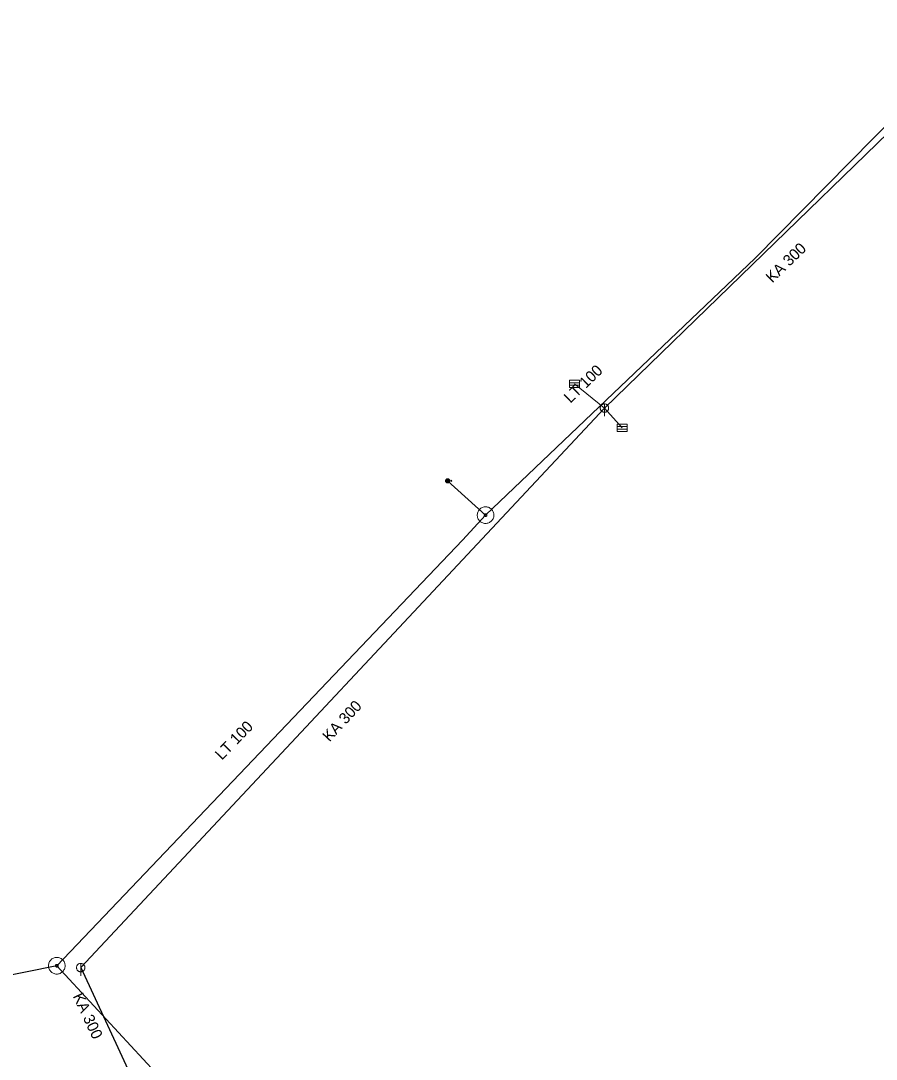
# Model space of a CAD drawing. Extents: x -687515 to -686506, y -974029 to -973461.
# Drawn here: x -687114.7 to -687063.3, y -973836.1 to -973773.7 of the extents above; entities that cross this region are included whole.
import ezdxf
from ezdxf.enums import TextEntityAlignment as Align

# ---------------------------------------------------------------- set-up
doc = ezdxf.new("R2010")
doc.units = 0
doc.header["$LTSCALE"] = 0.27
for name, color, linetype, lineweight in [('1', 7, 'Continuous', 13), ('11', 7, 'Continuous', 13), ('14', 7, 'Continuous', 25), ('17', 7, 'Continuous', 25), ('22', 7, 'Continuous', 13), ('47', 7, 'Continuous', 13), ('9', 7, 'Continuous', 13)]:
    doc.layers.add(name, color=color, linetype=linetype, lineweight=lineweight)

msp = doc.modelspace()

# ---------------------------------------------------------------- linework, layer by layer
at = {"layer": '11'}
for p in [(-687081.398, -973795.561), (-687078.524, -973798.199)]:
    msp.add_line(p, (-687079.592, -973797.014), dxfattribs=at)
at = {"layer": '14'}
for p, q in [((-687057.566, -973775.642), (-687079.592, -973797.014)), ((-687079.592, -973797.014), (-687111.064, -973830.634)), ((-687111.064, -973830.634), (-687107.04, -973839.305))]:
    msp.add_line(p, q, dxfattribs=at)
at = {"layer": '14', "lineweight": 13}
for p, q in [((-687086.733, -973803.447), (-687089.012, -973801.388)), ((-687106.566, -973836.941), (-687112.499, -973830.523))]:
    msp.add_line(p, q, dxfattribs=at)
at = {"layer": '17'}
for points in [[(-686989.707, -973753.404), (-687001.294, -973755.738), (-687033.846, -973763.506), (-687042.734, -973766.009), (-687045.081, -973767.522), (-687056.296, -973773.572), (-687070.532, -973788), (-687086.733, -973803.447)], [(-687112.499, -973830.523), (-687125.387, -973833.14), (-687131.526, -973833.246), (-687138.067, -973830.845), (-687146.977, -973822.133), (-687188.57, -973780.435), (-687198.6, -973770.76), (-687208.769, -973760.209)], [(-687086.733, -973803.447), (-687088.12, -973804.949), (-687112.499, -973830.523)]]:
    msp.add_lwpolyline(points, dxfattribs=at)
at = {"layer": '22'}
for p, q in [((-687081.693, -973795.49), (-687081.095, -973795.49)), ((-687081.693, -973795.636), (-687081.095, -973795.636)), ((-687079.591, -973796.762), (-687079.592, -973797.505)), ((-687078.819, -973798.128), (-687078.221, -973798.128)), ((-687078.819, -973798.274), (-687078.221, -973798.274)), ((-687111.063, -973830.382), (-687111.064, -973831.125))]:
    msp.add_line(p, q, dxfattribs=at)
for points in [[(-687081.693, -973795.344), (-687081.095, -973795.344), (-687081.095, -973795.781), (-687081.693, -973795.781)], [(-687079.34, -973797.014), (-687079.341, -973796.988), (-687079.345, -973796.962), (-687079.351, -973796.936), (-687079.361, -973796.912), (-687079.373, -973796.888), (-687079.387, -973796.866), (-687079.404, -973796.845), (-687079.422, -973796.827), (-687079.443, -973796.81), (-687079.465, -973796.796), (-687079.489, -973796.784), (-687079.513, -973796.774), (-687079.539, -973796.768), (-687079.565, -973796.764), (-687079.591, -973796.762), (-687079.617, -973796.763), (-687079.643, -973796.767), (-687079.669, -973796.773), (-687079.694, -973796.783), (-687079.717, -973796.795), (-687079.739, -973796.809), (-687079.76, -973796.826), (-687079.778, -973796.844), (-687079.795, -973796.865), (-687079.809, -973796.887), (-687079.821, -973796.911), (-687079.831, -973796.935), (-687079.838, -973796.961), (-687079.842, -973796.987), (-687079.843, -973797.013), (-687079.843, -973797.039), (-687079.839, -973797.065), (-687079.832, -973797.091), (-687079.822, -973797.116), (-687079.81, -973797.139), (-687079.796, -973797.161), (-687079.779, -973797.182), (-687079.761, -973797.2), (-687079.74, -973797.217), (-687079.718, -973797.231), (-687079.695, -973797.243), (-687079.67, -973797.253), (-687079.644, -973797.26), (-687079.618, -973797.264), (-687079.592, -973797.266), (-687079.566, -973797.265), (-687079.54, -973797.261), (-687079.514, -973797.254), (-687079.49, -973797.244), (-687079.466, -973797.232), (-687079.444, -973797.218), (-687079.423, -973797.201), (-687079.405, -973797.183), (-687079.388, -973797.162), (-687079.374, -973797.14), (-687079.362, -973797.117), (-687079.352, -973797.092), (-687079.346, -973797.066), (-687079.342, -973797.04)], [(-687078.819, -973797.982), (-687078.221, -973797.982), (-687078.221, -973798.419), (-687078.819, -973798.419)], [(-687110.812, -973830.634), (-687110.813, -973830.608), (-687110.817, -973830.582), (-687110.823, -973830.556), (-687110.833, -973830.532), (-687110.845, -973830.508), (-687110.859, -973830.486), (-687110.876, -973830.465), (-687110.894, -973830.447), (-687110.915, -973830.43), (-687110.937, -973830.416), (-687110.961, -973830.404), (-687110.985, -973830.394), (-687111.011, -973830.388), (-687111.037, -973830.384), (-687111.063, -973830.382), (-687111.089, -973830.383), (-687111.115, -973830.387), (-687111.141, -973830.393), (-687111.166, -973830.403), (-687111.189, -973830.415), (-687111.211, -973830.429), (-687111.232, -973830.446), (-687111.25, -973830.464), (-687111.267, -973830.485), (-687111.281, -973830.507), (-687111.293, -973830.531), (-687111.303, -973830.555), (-687111.31, -973830.581), (-687111.314, -973830.607), (-687111.316, -973830.633), (-687111.315, -973830.659), (-687111.311, -973830.685), (-687111.304, -973830.711), (-687111.294, -973830.736), (-687111.282, -973830.759), (-687111.268, -973830.781), (-687111.251, -973830.802), (-687111.233, -973830.82), (-687111.212, -973830.837), (-687111.19, -973830.851), (-687111.167, -973830.863), (-687111.142, -973830.873), (-687111.116, -973830.88), (-687111.09, -973830.884), (-687111.064, -973830.886), (-687111.038, -973830.885), (-687111.012, -973830.881), (-687110.986, -973830.874), (-687110.962, -973830.864), (-687110.938, -973830.852), (-687110.916, -973830.838), (-687110.895, -973830.821), (-687110.877, -973830.803), (-687110.86, -973830.782), (-687110.846, -973830.76), (-687110.834, -973830.737), (-687110.824, -973830.712), (-687110.818, -973830.686), (-687110.814, -973830.66)]]:
    msp.add_lwpolyline(points, close=True, dxfattribs=at)
at = {"layer": '47'}
for points in [[(-687086.426, -973803.051), (-687086.469, -973803.022), (-687086.515, -973802.996), (-687086.564, -973802.977), (-687086.613, -973802.961), (-687086.665, -973802.951), (-687086.718, -973802.947), (-687086.77, -973802.949), (-687086.821, -973802.955), (-687086.872, -973802.967), (-687086.922, -973802.984), (-687086.97, -973803.006), (-687087.014, -973803.034), (-687087.056, -973803.065), (-687087.094, -973803.101), (-687087.128, -973803.14), (-687087.157, -973803.183), (-687087.183, -973803.229), (-687087.203, -973803.278), (-687087.218, -973803.327), (-687087.228, -973803.379), (-687087.232, -973803.432), (-687087.231, -973803.484), (-687087.224, -973803.536), (-687087.213, -973803.587), (-687087.195, -973803.636), (-687087.173, -973803.684), (-687087.146, -973803.729), (-687087.114, -973803.77), (-687087.078, -973803.808), (-687087.039, -973803.842), (-687086.996, -973803.871), (-687086.95, -973803.897), (-687086.901, -973803.918), (-687086.852, -973803.932), (-687086.8, -973803.942), (-687086.748, -973803.947), (-687086.695, -973803.946), (-687086.643, -973803.939), (-687086.592, -973803.927), (-687086.543, -973803.909), (-687086.495, -973803.887), (-687086.451, -973803.86), (-687086.409, -973803.828), (-687086.371, -973803.792), (-687086.337, -973803.753), (-687086.308, -973803.71), (-687086.282, -973803.664), (-687086.262, -973803.616), (-687086.247, -973803.566), (-687086.237, -973803.514), (-687086.232, -973803.462), (-687086.234, -973803.41), (-687086.241, -973803.358), (-687086.253, -973803.307), (-687086.27, -973803.257), (-687086.292, -973803.209), (-687086.319, -973803.166), (-687086.351, -973803.123), (-687086.387, -973803.085)], [(-687086.682, -973803.382), (-687086.689, -973803.376), (-687086.697, -973803.373), (-687086.705, -973803.37), (-687086.713, -973803.367), (-687086.721, -973803.365), (-687086.73, -973803.365), (-687086.739, -973803.365), (-687086.747, -973803.366), (-687086.755, -973803.368), (-687086.764, -973803.371), (-687086.772, -973803.375), (-687086.779, -973803.379), (-687086.785, -973803.384), (-687086.792, -973803.389), (-687086.797, -973803.396), (-687086.803, -973803.403), (-687086.806, -973803.411), (-687086.809, -973803.419), (-687086.812, -973803.427), (-687086.814, -973803.435), (-687086.814, -973803.444), (-687086.814, -973803.453), (-687086.813, -973803.461), (-687086.811, -973803.47), (-687086.808, -973803.478), (-687086.804, -973803.486), (-687086.8, -973803.493), (-687086.795, -973803.499), (-687086.79, -973803.506), (-687086.783, -973803.511), (-687086.776, -973803.517), (-687086.768, -973803.52), (-687086.76, -973803.523), (-687086.752, -973803.526), (-687086.744, -973803.528), (-687086.736, -973803.529), (-687086.726, -973803.528), (-687086.718, -973803.527), (-687086.709, -973803.525), (-687086.701, -973803.522), (-687086.693, -973803.518), (-687086.686, -973803.514), (-687086.68, -973803.509), (-687086.673, -973803.504), (-687086.668, -973803.497), (-687086.662, -973803.49), (-687086.659, -973803.482), (-687086.656, -973803.474), (-687086.653, -973803.466), (-687086.651, -973803.458), (-687086.65, -973803.45), (-687086.651, -973803.44), (-687086.652, -973803.432), (-687086.654, -973803.424), (-687086.657, -973803.415), (-687086.661, -973803.407), (-687086.665, -973803.4), (-687086.67, -973803.394), (-687086.675, -973803.387)], [(-687112.123, -973830.192), (-687112.16, -973830.155), (-687112.2, -973830.122), (-687112.243, -973830.093), (-687112.289, -973830.068), (-687112.338, -973830.049), (-687112.389, -973830.035), (-687112.44, -973830.027), (-687112.493, -973830.023), (-687112.544, -973830.025), (-687112.597, -973830.032), (-687112.648, -973830.045), (-687112.696, -973830.064), (-687112.743, -973830.087), (-687112.788, -973830.115), (-687112.829, -973830.147), (-687112.866, -973830.184), (-687112.899, -973830.224), (-687112.929, -973830.268), (-687112.953, -973830.313), (-687112.972, -973830.362), (-687112.986, -973830.413), (-687112.995, -973830.465), (-687112.998, -973830.517), (-687112.997, -973830.569), (-687112.989, -973830.621), (-687112.976, -973830.672), (-687112.958, -973830.721), (-687112.934, -973830.767), (-687112.906, -973830.812), (-687112.874, -973830.853), (-687112.837, -973830.89), (-687112.797, -973830.923), (-687112.754, -973830.953), (-687112.708, -973830.977), (-687112.659, -973830.996), (-687112.609, -973831.011), (-687112.557, -973831.02), (-687112.505, -973831.023), (-687112.452, -973831.021), (-687112.4, -973831.013), (-687112.349, -973831), (-687112.301, -973830.982), (-687112.254, -973830.958), (-687112.209, -973830.93), (-687112.168, -973830.898), (-687112.131, -973830.861), (-687112.098, -973830.821), (-687112.069, -973830.778), (-687112.044, -973830.732), (-687112.025, -973830.683), (-687112.01, -973830.633), (-687112.002, -973830.581), (-687111.999, -973830.529), (-687112.001, -973830.477), (-687112.008, -973830.424), (-687112.021, -973830.373), (-687112.039, -973830.325), (-687112.063, -973830.278), (-687112.091, -973830.233)], [(-687112.437, -973830.468), (-687112.443, -973830.462), (-687112.45, -973830.457), (-687112.456, -973830.452), (-687112.464, -973830.448), (-687112.472, -973830.445), (-687112.481, -973830.443), (-687112.489, -973830.441), (-687112.497, -973830.44), (-687112.506, -973830.441), (-687112.515, -973830.442), (-687112.523, -973830.444), (-687112.531, -973830.447), (-687112.539, -973830.451), (-687112.546, -973830.455), (-687112.553, -973830.461), (-687112.559, -973830.467), (-687112.564, -973830.474), (-687112.569, -973830.48), (-687112.573, -973830.488), (-687112.576, -973830.496), (-687112.578, -973830.505), (-687112.58, -973830.513), (-687112.581, -973830.521), (-687112.581, -973830.531), (-687112.579, -973830.539), (-687112.577, -973830.547), (-687112.574, -973830.555), (-687112.57, -973830.563), (-687112.566, -973830.57), (-687112.56, -973830.577), (-687112.554, -973830.583), (-687112.547, -973830.588), (-687112.541, -973830.593), (-687112.533, -973830.597), (-687112.525, -973830.6), (-687112.517, -973830.603), (-687112.508, -973830.604), (-687112.5, -973830.605), (-687112.49, -973830.605), (-687112.482, -973830.603), (-687112.474, -973830.601), (-687112.466, -973830.598), (-687112.458, -973830.594), (-687112.451, -973830.59), (-687112.444, -973830.584), (-687112.438, -973830.578), (-687112.433, -973830.571), (-687112.428, -973830.565), (-687112.424, -973830.557), (-687112.421, -973830.549), (-687112.418, -973830.541), (-687112.417, -973830.532), (-687112.416, -973830.524), (-687112.417, -973830.515), (-687112.418, -973830.506), (-687112.42, -973830.498), (-687112.423, -973830.49), (-687112.427, -973830.482), (-687112.431, -973830.475)]]:
    msp.add_lwpolyline(points, close=True, dxfattribs=at)
at = {"layer": '9'}
msp.add_line((-687088.886, -973801.388), (-687088.76, -973801.388), dxfattribs=at)
for points in [[(-687089.012, -973801.514), (-687088.999, -973801.513), (-687088.986, -973801.511), (-687088.973, -973801.508), (-687088.961, -973801.503), (-687088.949, -973801.497), (-687088.938, -973801.49), (-687088.928, -973801.482), (-687088.918, -973801.472), (-687088.91, -973801.462), (-687088.903, -973801.451), (-687088.897, -973801.439), (-687088.892, -973801.427), (-687088.889, -973801.414), (-687088.887, -973801.401), (-687088.886, -973801.388), (-687088.886, -973801.375), (-687088.888, -973801.362), (-687088.891, -973801.349), (-687088.896, -973801.337), (-687088.902, -973801.325), (-687088.909, -973801.314), (-687088.917, -973801.304), (-687088.927, -973801.294), (-687088.937, -973801.286), (-687088.948, -973801.279), (-687088.96, -973801.273), (-687088.972, -973801.268), (-687088.985, -973801.265), (-687088.998, -973801.263), (-687089.011, -973801.262), (-687089.024, -973801.262), (-687089.037, -973801.264), (-687089.05, -973801.267), (-687089.062, -973801.272), (-687089.074, -973801.278), (-687089.085, -973801.285), (-687089.095, -973801.293), (-687089.105, -973801.303), (-687089.113, -973801.313), (-687089.12, -973801.324), (-687089.126, -973801.336), (-687089.131, -973801.348), (-687089.134, -973801.361), (-687089.136, -973801.374), (-687089.138, -973801.387), (-687089.137, -973801.4), (-687089.135, -973801.413), (-687089.132, -973801.426), (-687089.127, -973801.438), (-687089.121, -973801.45), (-687089.114, -973801.461), (-687089.106, -973801.471), (-687089.096, -973801.481), (-687089.086, -973801.489), (-687089.075, -973801.496), (-687089.063, -973801.502), (-687089.051, -973801.507), (-687089.038, -973801.51), (-687089.025, -973801.512)], [(-687089.012, -973801.494), (-687089.001, -973801.494), (-687088.99, -973801.492), (-687088.979, -973801.489), (-687088.969, -973801.485), (-687088.959, -973801.48), (-687088.95, -973801.474), (-687088.941, -973801.467), (-687088.933, -973801.459), (-687088.926, -973801.45), (-687088.92, -973801.441), (-687088.915, -973801.431), (-687088.911, -973801.421), (-687088.908, -973801.41), (-687088.906, -973801.399), (-687088.906, -973801.388), (-687088.905, -973801.377), (-687088.907, -973801.366), (-687088.91, -973801.355), (-687088.914, -973801.345), (-687088.919, -973801.335), (-687088.925, -973801.326), (-687088.932, -973801.317), (-687088.94, -973801.309), (-687088.949, -973801.302), (-687088.958, -973801.296), (-687088.968, -973801.291), (-687088.978, -973801.287), (-687088.989, -973801.284), (-687089, -973801.282), (-687089.011, -973801.282), (-687089.022, -973801.281), (-687089.033, -973801.283), (-687089.044, -973801.286), (-687089.054, -973801.29), (-687089.064, -973801.295), (-687089.073, -973801.301), (-687089.082, -973801.308), (-687089.09, -973801.316), (-687089.097, -973801.325), (-687089.103, -973801.334), (-687089.108, -973801.344), (-687089.112, -973801.354), (-687089.115, -973801.365), (-687089.117, -973801.376), (-687089.118, -973801.387), (-687089.118, -973801.398), (-687089.116, -973801.409), (-687089.113, -973801.42), (-687089.109, -973801.43), (-687089.104, -973801.44), (-687089.098, -973801.449), (-687089.091, -973801.458), (-687089.083, -973801.466), (-687089.074, -973801.473), (-687089.065, -973801.479), (-687089.055, -973801.484), (-687089.045, -973801.488), (-687089.034, -973801.491), (-687089.023, -973801.493)], [(-687089.012, -973801.475), (-687089.003, -973801.474), (-687088.994, -973801.473), (-687088.985, -973801.47), (-687088.977, -973801.467), (-687088.969, -973801.463), (-687088.961, -973801.458), (-687088.954, -973801.452), (-687088.948, -973801.446), (-687088.942, -973801.439), (-687088.937, -973801.431), (-687088.933, -973801.423), (-687088.93, -973801.415), (-687088.927, -973801.406), (-687088.926, -973801.397), (-687088.924, -973801.388), (-687088.925, -973801.379), (-687088.926, -973801.37), (-687088.929, -973801.361), (-687088.932, -973801.353), (-687088.936, -973801.345), (-687088.941, -973801.337), (-687088.947, -973801.33), (-687088.953, -973801.324), (-687088.96, -973801.318), (-687088.968, -973801.313), (-687088.976, -973801.309), (-687088.984, -973801.306), (-687088.993, -973801.303), (-687089.002, -973801.302), (-687089.011, -973801.301), (-687089.02, -973801.301), (-687089.029, -973801.302), (-687089.038, -973801.305), (-687089.046, -973801.308), (-687089.054, -973801.312), (-687089.062, -973801.317), (-687089.069, -973801.323), (-687089.075, -973801.329), (-687089.081, -973801.336), (-687089.086, -973801.344), (-687089.09, -973801.352), (-687089.093, -973801.36), (-687089.096, -973801.369), (-687089.097, -973801.378), (-687089.099, -973801.387), (-687089.098, -973801.396), (-687089.097, -973801.405), (-687089.094, -973801.414), (-687089.091, -973801.422), (-687089.087, -973801.43), (-687089.082, -973801.438), (-687089.076, -973801.445), (-687089.07, -973801.451), (-687089.063, -973801.457), (-687089.055, -973801.462), (-687089.047, -973801.466), (-687089.039, -973801.469), (-687089.03, -973801.472), (-687089.021, -973801.473)], [(-687089.012, -973801.455), (-687089.005, -973801.455), (-687088.998, -973801.453), (-687088.991, -973801.452), (-687088.985, -973801.449), (-687088.979, -973801.446), (-687088.973, -973801.442), (-687088.967, -973801.438), (-687088.962, -973801.433), (-687088.958, -973801.427), (-687088.954, -973801.421), (-687088.951, -973801.415), (-687088.948, -973801.409), (-687088.947, -973801.402), (-687088.945, -973801.395), (-687088.945, -973801.388), (-687088.944, -973801.381), (-687088.946, -973801.374), (-687088.947, -973801.367), (-687088.95, -973801.361), (-687088.953, -973801.354), (-687088.957, -973801.349), (-687088.961, -973801.343), (-687088.966, -973801.338), (-687088.972, -973801.334), (-687088.978, -973801.33), (-687088.984, -973801.327), (-687088.99, -973801.324), (-687088.997, -973801.322), (-687089.004, -973801.321), (-687089.011, -973801.321), (-687089.018, -973801.32), (-687089.025, -973801.321), (-687089.032, -973801.323), (-687089.038, -973801.326), (-687089.045, -973801.329), (-687089.05, -973801.333), (-687089.056, -973801.337), (-687089.061, -973801.342), (-687089.065, -973801.348), (-687089.069, -973801.353), (-687089.072, -973801.36), (-687089.075, -973801.366), (-687089.077, -973801.373), (-687089.078, -973801.38), (-687089.079, -973801.387), (-687089.079, -973801.394), (-687089.078, -973801.401), (-687089.076, -973801.408), (-687089.073, -973801.414), (-687089.07, -973801.42), (-687089.066, -973801.426), (-687089.062, -973801.432), (-687089.057, -973801.437), (-687089.051, -973801.441), (-687089.046, -973801.445), (-687089.039, -973801.448), (-687089.033, -973801.451), (-687089.026, -973801.452), (-687089.019, -973801.454)], [(-687089.012, -973801.435), (-687089.007, -973801.435), (-687089.002, -973801.434), (-687088.997, -973801.433), (-687088.993, -973801.431), (-687088.988, -973801.429), (-687088.984, -973801.426), (-687088.981, -973801.423), (-687088.977, -973801.419), (-687088.974, -973801.416), (-687088.971, -973801.412), (-687088.969, -973801.407), (-687088.967, -973801.403), (-687088.966, -973801.398), (-687088.965, -973801.393), (-687088.965, -973801.388), (-687088.964, -973801.383), (-687088.965, -973801.378), (-687088.966, -973801.373), (-687088.968, -973801.369), (-687088.97, -973801.364), (-687088.973, -973801.36), (-687088.976, -973801.356), (-687088.98, -973801.353), (-687088.983, -973801.35), (-687088.987, -973801.347), (-687088.992, -973801.345), (-687088.996, -973801.343), (-687089.001, -973801.342), (-687089.006, -973801.341), (-687089.011, -973801.341), (-687089.016, -973801.34), (-687089.021, -973801.341), (-687089.026, -973801.342), (-687089.03, -973801.344), (-687089.035, -973801.346), (-687089.039, -973801.349), (-687089.043, -973801.352), (-687089.046, -973801.355), (-687089.049, -973801.359), (-687089.052, -973801.363), (-687089.054, -973801.368), (-687089.056, -973801.372), (-687089.057, -973801.377), (-687089.058, -973801.382), (-687089.059, -973801.387), (-687089.059, -973801.392), (-687089.058, -973801.397), (-687089.057, -973801.402), (-687089.055, -973801.406), (-687089.053, -973801.411), (-687089.05, -973801.415), (-687089.047, -973801.418), (-687089.044, -973801.422), (-687089.04, -973801.425), (-687089.036, -973801.428), (-687089.031, -973801.43), (-687089.027, -973801.432), (-687089.022, -973801.433), (-687089.017, -973801.434)], [(-687089.012, -973801.415), (-687089.009, -973801.415), (-687089.006, -973801.415), (-687089.004, -973801.414), (-687089.001, -973801.413), (-687088.998, -973801.412), (-687088.996, -973801.41), (-687088.994, -973801.408), (-687088.992, -973801.406), (-687088.99, -973801.404), (-687088.988, -973801.402), (-687088.987, -973801.399), (-687088.986, -973801.396), (-687088.985, -973801.394), (-687088.985, -973801.391), (-687088.985, -973801.388), (-687088.984, -973801.385), (-687088.984, -973801.382), (-687088.985, -973801.379), (-687088.986, -973801.377), (-687088.987, -973801.374), (-687088.989, -973801.372), (-687088.991, -973801.369), (-687088.993, -973801.367), (-687088.995, -973801.366), (-687088.997, -973801.364), (-687089, -973801.363), (-687089.003, -973801.362), (-687089.005, -973801.361), (-687089.008, -973801.361), (-687089.011, -973801.36), (-687089.014, -973801.36), (-687089.017, -973801.36), (-687089.02, -973801.361), (-687089.022, -973801.362), (-687089.025, -973801.363), (-687089.027, -973801.365), (-687089.03, -973801.366), (-687089.032, -973801.368), (-687089.033, -973801.371), (-687089.035, -973801.373), (-687089.036, -973801.376), (-687089.037, -973801.378), (-687089.038, -973801.381), (-687089.038, -973801.384), (-687089.04, -973801.387), (-687089.039, -973801.39), (-687089.039, -973801.393), (-687089.038, -973801.395), (-687089.037, -973801.398), (-687089.036, -973801.401), (-687089.034, -973801.403), (-687089.033, -973801.405), (-687089.031, -973801.407), (-687089.028, -973801.409), (-687089.026, -973801.411), (-687089.023, -973801.412), (-687089.021, -973801.413), (-687089.018, -973801.414), (-687089.015, -973801.414)], [(-687089.012, -973801.396), (-687089.011, -973801.396), (-687089.01, -973801.396), (-687089.01, -973801.395), (-687089.009, -973801.395), (-687089.008, -973801.395), (-687089.007, -973801.394), (-687089.007, -973801.394), (-687089.006, -973801.393), (-687089.006, -973801.393), (-687089.005, -973801.392), (-687089.005, -973801.391), (-687089.005, -973801.39), (-687089.004, -973801.39), (-687089.004, -973801.389), (-687089.004, -973801.388), (-687089.004, -973801.387), (-687089.004, -973801.386), (-687089.004, -973801.386), (-687089.004, -973801.385), (-687089.004, -973801.384), (-687089.005, -973801.383), (-687089.005, -973801.383), (-687089.006, -973801.382), (-687089.006, -973801.382), (-687089.007, -973801.381), (-687089.008, -973801.381), (-687089.009, -973801.38), (-687089.009, -973801.38), (-687089.01, -973801.38), (-687089.011, -973801.38), (-687089.012, -973801.38), (-687089.013, -973801.38), (-687089.013, -973801.38), (-687089.014, -973801.38), (-687089.015, -973801.38), (-687089.016, -973801.381), (-687089.016, -973801.381), (-687089.017, -973801.382), (-687089.017, -973801.382), (-687089.018, -973801.383), (-687089.018, -973801.384), (-687089.019, -973801.385), (-687089.019, -973801.385), (-687089.019, -973801.386), (-687089.02, -973801.387), (-687089.02, -973801.388), (-687089.02, -973801.389), (-687089.02, -973801.389), (-687089.019, -973801.39), (-687089.019, -973801.391), (-687089.018, -973801.392), (-687089.018, -973801.392), (-687089.017, -973801.393), (-687089.017, -973801.393), (-687089.016, -973801.394), (-687089.015, -973801.394), (-687089.014, -973801.394), (-687089.014, -973801.396), (-687089.013, -973801.396)]]:
    msp.add_lwpolyline(points, close=True, dxfattribs=at)
msp.add_lwpolyline([(-687088.794, -973801.357), (-687088.76, -973801.388), (-687088.795, -973801.419)], dxfattribs=at)

# ---------------------------------------------------------------- texts
at = {"layer": '1'}
for s, rotation, p in [('KA 300', 44, (-687068.459, -973788.513)), ('LT 100', 44, (-687080.64, -973795.794)), ('KA 300', 47, (-687095.118, -973816.035)), ('LT 100', 46, (-687101.615, -973817.205)), ('KA 300', 295, (-687110.934, -973833.672))]:
    msp.add_text(s, height=0.6667, rotation=rotation, dxfattribs=at).set_placement(p, align=Align.CENTER)

doc.saveas('drawing.dxf')
